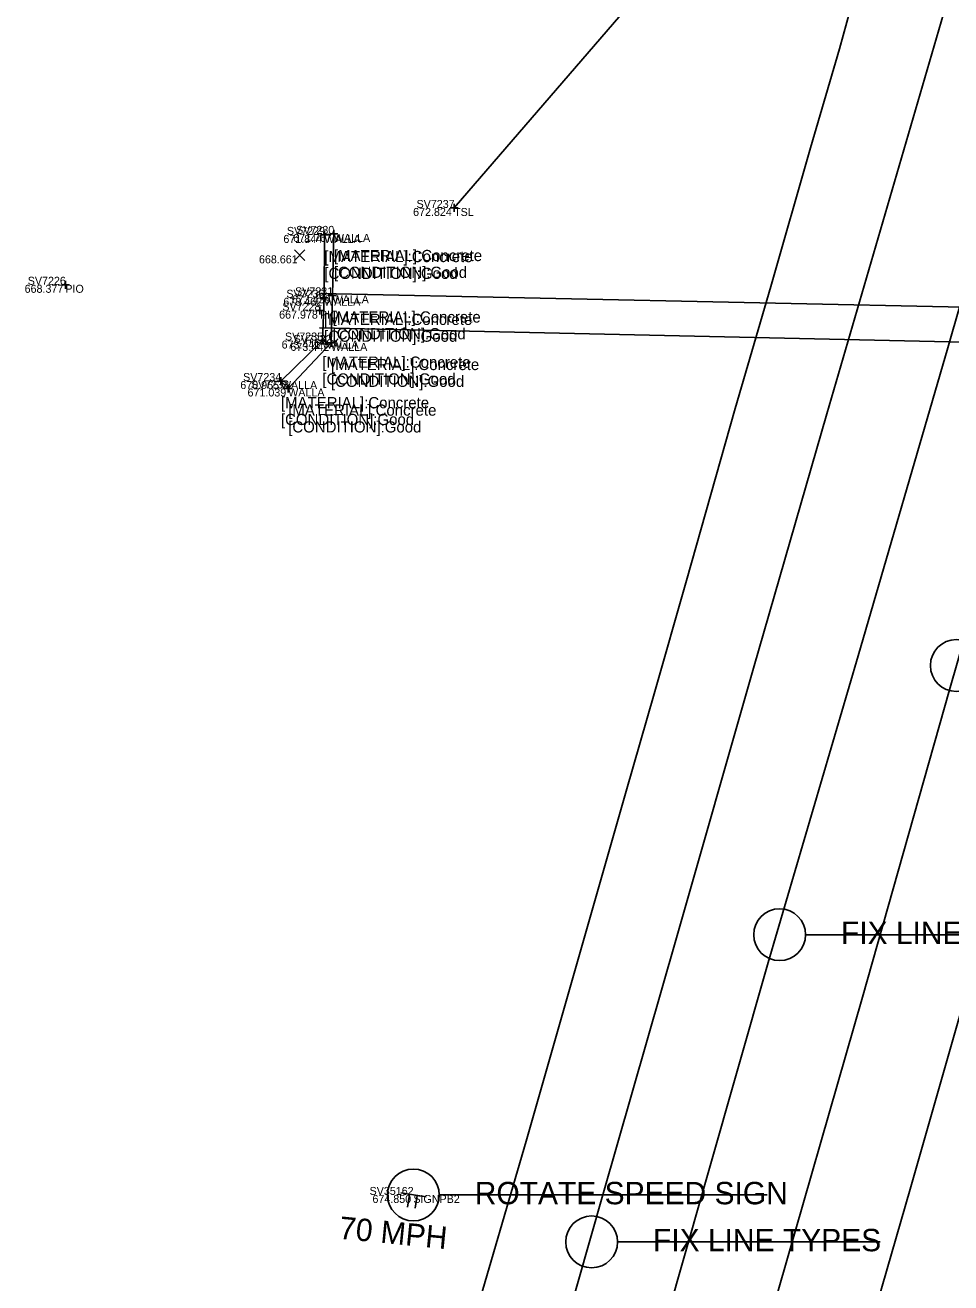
# Model space of a CAD drawing. Extents: x 1659932 to 1663108, y 619867 to 620611.
# Drawn here: x 1661183.6 to 1661299.3, y 620035.3 to 620192.5 of the extents above; entities that cross this region are included whole.
import ezdxf

# ---------------------------------------------------------------- set-up
doc = ezdxf.new("R2010")
doc.units = 0
for name, color, linetype in [('BR_X_SV_Abut', 7, 'Continuous'), ('BR_X_SV_Abut_Text', 7, 'Continuous'), ('DR_X_Culvert', 7, 'Continuous'), ('DR_X_Elev_Flow', 7, 'Continuous'), ('PM_X_Edge_Line', 7, 'Continuous'), ('PM_X_Lane_Line', 7, 'Continuous'), ('PV_X_EOP', 7, 'Continuous'), ('RD_X_Text', 7, 'Continuous'), ('SC_Scratch6', 7, 'Continuous'), ('SN_X_Public', 7, 'Continuous'), ('SV_X_Random_Point', 7, 'Continuous'), ('SV_X_Shot_Marker', 7, 'Continuous'), ('SV_X_Text', 7, 'Continuous'), ('SV_X_Text_Comment', 7, 'Continuous'), ('SV_X_Text_Elevation', 7, 'Continuous'), ('SV_X_Text_Name', 7, 'Continuous'), ('SV_X_Toe_of_Slope', 7, 'Continuous')]:
    doc.layers.add(name, color=color, linetype=linetype)

msp = doc.modelspace()

# ---------------------------------------------------------------- linework, layer by layer
at = {"layer": 'BR_X_SV_Abut'}
msp.add_lwpolyline([(1661221.02, 620166.27), (1661222.21, 620166.4), (1661222.04, 620158.72), (1661221.85, 620152.78), (1661216.5, 620147.08), (1661215.59, 620148.01), (1661220.77, 620153.07), (1661220.98, 620158.42)], close=True, dxfattribs=at)
at = {"layer": 'DR_X_Culvert'}
for p, q in [((1661220.52, 620158.97), (1661487.86, 620153.16)), ((1661220.42, 620154.64), (1661487.76, 620148.82))]:
    msp.add_line(p, q, dxfattribs=at)
at = {"layer": 'DR_X_Elev_Flow'}
for p, q in [((1661188.16, 620160.04), (1661189.16, 620160.04)), ((1661188.66, 620160.54), (1661188.66, 620159.54)), ((1661188.66, 620160.04), (1661188.66, 620160.04)), ((1661219.97, 620156.81), (1661220.97, 620156.81)), ((1661220.47, 620157.31), (1661220.47, 620156.31)), ((1661220.47, 620156.81), (1661220.47, 620156.81))]:
    msp.add_line(p, q, dxfattribs=at)
at = {"layer": 'PM_X_Edge_Line'}
for points in [[(1661205.76, 619869.48), (1661211.13, 619888.81), (1661217.41, 619910.98), (1661224.34, 619935.2), (1661231.75, 619961.45), (1661235.51, 619974.89), (1661240.67, 619993.15), (1661247.93, 620018.65), (1661255.82, 620046.31), (1661265.01, 620078.44), (1661274.65, 620112.11), (1661283.8, 620143.93), (1661298.65, 620194.91), (1661304.26, 620213.97)], [(1661341.94, 620213.22), (1661337.31, 620197.39), (1661326.5, 620160.05), (1661314.91, 620119.7), (1661309.67, 620101.22), (1661301.86, 620073.85), (1661294.2, 620047.04), (1661286.06, 620018.73), (1661279.32, 619995.43), (1661269.93, 619963.07), (1661260.59, 619930.4), (1661255.64, 619912.95), (1661249.95, 619892.74), (1661243.97, 619871.61)]]:
    msp.add_lwpolyline(points, dxfattribs=at)
at = {"layer": 'PM_X_Lane_Line'}
for points in [[(1661221.59, 619881.87), (1661232.5, 619920.16), (1661243.45, 619958.79), (1661254.55, 619998.19), (1661265.28, 620036.08), (1661276.49, 620075.34), (1661287.7, 620113.67), (1661298.9, 620152.14), (1661309.87, 620190.36)], [(1661233.25, 619878.6), (1661244.2, 619917.52), (1661254.62, 619954.7), (1661265.49, 619992.35), (1661276.71, 620030.87), (1661288.27, 620071), (1661299.13, 620109.41), (1661309.52, 620145.68), (1661321.42, 620186.85)]]:
    msp.add_lwpolyline(points, dxfattribs=at)
at = {"layer": 'PV_X_EOP'}
msp.add_lwpolyline([(1661194.33, 619870.94), (1661199.12, 619888.31), (1661202.83, 619901.54), (1661213.74, 619940), (1661227.28, 619987.12), (1661233.26, 620009.06), (1661239.44, 620029.76), (1661246.23, 620053.02), (1661255.14, 620084.21), (1661258.72, 620096.74), (1661262.23, 620108.92), (1661266.25, 620123.09), (1661272.33, 620144.56), (1661276.82, 620159.81), (1661281.77, 620177.17), (1661285.4, 620189.51), (1661287.68, 620197.89), (1661288.91, 620201.99), (1661291.15, 620209.79), (1661292.37, 620214.09)], dxfattribs=at)
at = {"layer": 'SC_Scratch6'}
for p, q in [((1661281.14, 620078.82), (1661313.95, 620078.82)), ((1661235.38, 620046.3), (1661276.34, 620046.3)), ((1661257.65, 620040.43), (1661290.45, 620040.43))]:
    msp.add_line(p, q, dxfattribs=at)
for centre in [(1661299.98, 620112.46), (1661277.9, 620078.82), (1661232.14, 620046.3), (1661254.41, 620040.43)]:
    msp.add_circle(centre, 3.24, dxfattribs=at)
at = {"layer": 'SN_X_Public'}
for p, q in [((1661230.56, 620046.55), (1661233.72, 620046.05)), ((1661231.67, 620046.37), (1661231.42, 620044.79)), ((1661232.14, 620046.3), (1661232.14, 620046.3)), ((1661232.61, 620046.23), (1661232.37, 620044.65))]:
    msp.add_line(p, q, dxfattribs=at)
at = {"layer": 'SV_X_Random_Point'}
for p, q in [((1661217.27, 620163.06), (1661218.6, 620164.39)), ((1661217.27, 620164.39), (1661218.6, 620163.06))]:
    msp.add_line(p, q, dxfattribs=at)
at = {"layer": 'SV_X_Shot_Marker'}
for p, q in [((1661236.73, 620169.64), (1661237.73, 620169.64)), ((1661237.23, 620170.14), (1661237.23, 620169.14)), ((1661237.23, 620169.64), (1661237.23, 620169.64)), ((1661220.52, 620166.27), (1661221.52, 620166.27)), ((1661221.02, 620166.77), (1661221.02, 620165.77)), ((1661221.02, 620166.27), (1661221.02, 620166.27)), ((1661221.71, 620166.4), (1661222.71, 620166.4)), ((1661222.21, 620166.9), (1661222.21, 620165.9)), ((1661222.21, 620166.4), (1661222.21, 620166.4)), ((1661220.48, 620158.42), (1661221.48, 620158.42)), ((1661220.98, 620158.92), (1661220.98, 620157.92)), ((1661220.98, 620158.42), (1661220.98, 620158.42)), ((1661221.54, 620158.72), (1661222.54, 620158.72)), ((1661222.04, 620159.22), (1661222.04, 620158.22)), ((1661222.04, 620158.72), (1661222.04, 620158.72)), ((1661220.27, 620153.07), (1661221.27, 620153.07)), ((1661220.77, 620153.57), (1661220.77, 620152.57)), ((1661220.77, 620153.07), (1661220.77, 620153.07)), ((1661221.35, 620152.78), (1661222.35, 620152.78)), ((1661221.85, 620153.28), (1661221.85, 620152.28)), ((1661221.85, 620152.78), (1661221.85, 620152.78)), ((1661215.09, 620148.01), (1661216.09, 620148.01)), ((1661215.59, 620148.51), (1661215.59, 620147.51)), ((1661215.59, 620148.01), (1661215.59, 620148.01)), ((1661216.5, 620147.58), (1661216.5, 620146.58)), ((1661216, 620147.08), (1661217, 620147.08)), ((1661216.5, 620147.08), (1661216.5, 620147.08))]:
    msp.add_line(p, q, dxfattribs=at)
at = {"layer": 'SV_X_Toe_of_Slope'}
msp.add_lwpolyline([(1661237.23, 620169.64), (1661259.66, 620195.62), (1661277.41, 620277.79), (1661264.31, 620300.27)], dxfattribs=at)

# ---------------------------------------------------------------- texts
at = {"layer": 'BR_X_SV_Abut_Text'}
for s, p in [('671.844', (1661215.9, 620165.27)), ('SV7229', (1661216.34, 620166.27)), ('671.767', (1661217.12, 620165.4)), ('SV7230', (1661217.5, 620166.4)), ('WALLA', (1661221.02, 620165.27)), ('WALLA', (1661222.21, 620165.4)), ('673.462', (1661215.9, 620157.42)), ('SV7236', (1661216.27, 620158.42)), ('673.439', (1661216.96, 620157.72)), ('SV7231', (1661217.36, 620158.72)), ('WALLA', (1661220.98, 620157.42)), ('WALLA', (1661222.04, 620157.72)), ('SV7235', (1661216.1, 620153.07)), ('SV7232', (1661217.18, 620152.78)), ('673.441', (1661215.68, 620152.07)), ('673.442', (1661216.78, 620151.78)), ('WALLA', (1661220.77, 620152.07)), ('WALLA', (1661221.85, 620151.78)), ('SV7234', (1661210.87, 620148.01)), ('670.965', (1661210.52, 620147.01)), ('SV7233', (1661211.84, 620147.08)), ('WALLA', (1661215.59, 620147.01)), ('671.039', (1661211.42, 620146.08)), ('WALLA', (1661216.5, 620146.08))]:
    msp.add_text(s, height=1, dxfattribs=at).set_placement(p)
at = {"layer": 'RD_X_Text'}
msp.add_text('70 MPH', height=2.8, rotation=354.3921, dxfattribs=at).set_placement((1661222.77, 620040.84))
at = {"layer": 'SC_Scratch6'}
for s, p in [('FIX LINE TYPES', (1661285.57, 620077.65)), ('ROTATE SPEED SIGN', (1661239.81, 620045.13)), ('FIX LINE TYPES', (1661262.08, 620039.26))]:
    msp.add_text(s, height=2.8, dxfattribs=at).set_placement(p)
at = {"layer": 'SV_X_Text'}
for s, p in [('[MATERIAL]:Concrete', (1661221.02, 620162.87)), ('[MATERIAL]:Concrete', (1661222.21, 620163)), ('[CONDITION]:Good', (1661221.02, 620160.77)), ('[CONDITION]:Good', (1661222.21, 620160.9)), ('[MATERIAL]:Concrete', (1661222.04, 620155.32)), ('[MATERIAL]:Concrete', (1661220.98, 620155.02)), ('[CONDITION]:Good', (1661220.98, 620152.92)), ('[CONDITION]:Good', (1661222.04, 620153.22)), ('[MATERIAL]:Concrete', (1661220.77, 620149.67)), ('[MATERIAL]:Concrete', (1661221.85, 620149.38)), ('[CONDITION]:Good', (1661220.77, 620147.57)), ('[CONDITION]:Good', (1661221.85, 620147.28)), ('[MATERIAL]:Concrete', (1661215.59, 620144.61)), ('[MATERIAL]:Concrete', (1661216.5, 620143.68)), ('[CONDITION]:Good', (1661215.59, 620142.51)), ('[CONDITION]:Good', (1661216.5, 620141.58))]:
    msp.add_text(s, height=1.4, dxfattribs=at).set_placement(p)
at = {"layer": 'SV_X_Text_Comment'}
for s, p in [('TSL', (1661237.23, 620168.64)), ('PIO', (1661188.66, 620159.04)), ('PIO', (1661220.47, 620155.81)), ('SIGNPB2', (1661232.14, 620045.3))]:
    msp.add_text(s, height=1, dxfattribs=at).set_placement(p)
at = {"layer": 'SV_X_Text_Elevation'}
for s, p in [('672.824', (1661232.11, 620168.64)), ('668.661', (1661212.85, 620162.72)), ('668.377', (1661183.57, 620159.04)), ('667.978', (1661215.37, 620155.81)), ('674.850', (1661227.03, 620045.3))]:
    msp.add_text(s, height=1, dxfattribs=at).set_placement(p)
at = {"layer": 'SV_X_Text_Name'}
for s, p in [('SV7237', (1661232.54, 620169.64)), ('SV7226', (1661183.96, 620160.04)), ('SV7228', (1661215.77, 620156.81)), ('SV35162', (1661226.67, 620046.3))]:
    msp.add_text(s, height=1, dxfattribs=at).set_placement(p)

doc.saveas('drawing.dxf')
